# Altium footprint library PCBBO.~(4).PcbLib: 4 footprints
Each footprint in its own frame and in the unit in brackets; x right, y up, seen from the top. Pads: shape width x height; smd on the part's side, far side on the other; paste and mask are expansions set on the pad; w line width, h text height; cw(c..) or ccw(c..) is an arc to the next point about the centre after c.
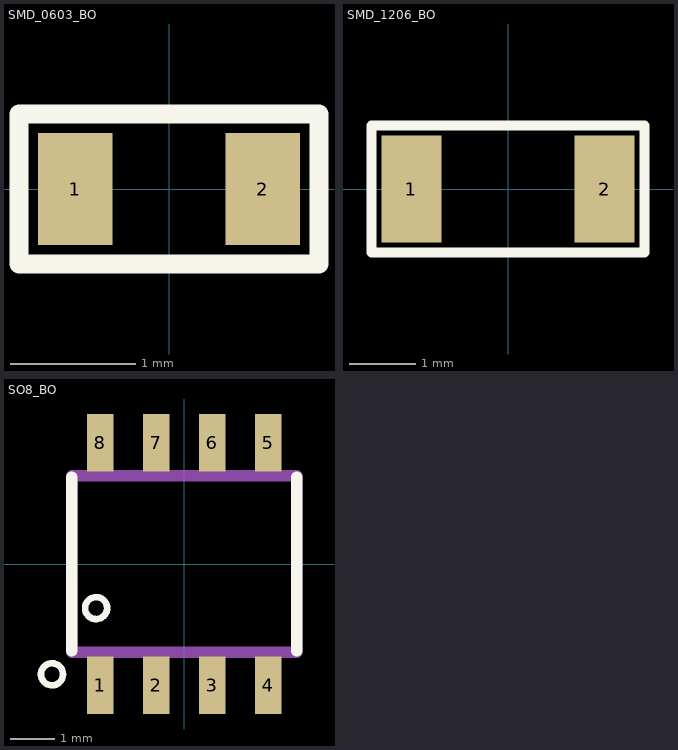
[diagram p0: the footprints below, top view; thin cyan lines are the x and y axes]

## SMD_0603_BO [mm]
pads (2):
  rect 0.6x0.9 smd: 1(-0.75,0) 2(0.75,0)
Top Overlay:
  lines w0.15: -1.2,-0.6 1.2,-0.6 1.2,0.6 -1.2,0.6 -1.2,-0.6
3D body "c0603c474k4ractu.stp": height 44.28, standoff 43.33, extent -97.458,10.644 -95.708,11.514
3D body "c0603c474k4ractu.stp": height 44.28, standoff 43.33, extent -97.458,10.644 -95.709,11.514
3D body: height 0.5, standoff 0, extent -0.775,-0.425 -0.372,0.425
3D body: height 0.5, standoff 0, extent 0.341,-0.425 0.744,0.425
3D body: height 0.5, standoff 0, extent -0.372,-0.425 0.341,0.425

## SMD_1206_BO [mm]
pads (2):
  rect 0.9x1.6 smd: 1(-1.45,0) 2(1.45,0)
Top Overlay:
  lines w0.15: -2.05,-0.95 2.05,-0.95 2.05,0.95 -2.05,0.95 -2.05,-0.95
3D body "c0603c474k4ractu.stp": height 44.28, standoff 43.33, extent -97.458,10.644 -95.708,11.514
3D body "c0603c474k4ractu.stp": height 44.28, standoff 43.33, extent -97.458,10.644 -95.709,11.514
3D body: height 0.5, standoff 0, extent -1.6,-0.8 -1,0.825
3D body: height 0.5, standoff 0, extent 1,-0.8 1.6,0.809
3D body: height 0.5, standoff 0, extent -1,-0.8 1,0.809

## SO8_BO [mm]
pads (8):
  rect 0.6x1.3 smd: 1(-1.905,-2.75) 2(-0.635,-2.75) 3(0.635,-2.75) 4(1.905,-2.75) 5(1.905,2.75) 6(0.635,2.75) 7(-0.635,2.75) 8(-1.905,2.75)
Top Overlay:
  circle w0.15: c-3,-2.5 r0.25
  circle w0.15: c-2,-1 r0.25
  lines w0.254: -2.55,-1.975 -2.55,1.975 ; 2.55,-1.975 2.55,1.975
Mechanical 13:
  lines w0.254: -2.55,-2 -2.55,2 2.55,2 2.55,-2 -2.55,-2
3D body "User Library-SOIC-8-1.step": height 1.75, standoff 0, extent -2.45,-3 2.45,3

## SOT23_BO [mm]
